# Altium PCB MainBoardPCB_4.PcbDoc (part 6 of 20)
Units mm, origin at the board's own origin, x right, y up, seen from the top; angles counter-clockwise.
Board outline 333.63 x 349.38 mm, 16 copper layers (L1, L2 (GND), L3 (Sign), L4 (GND), L5 (Sign), L6 (PWR/GND), L7(PWR/GND), L8 (Plane_GND), L9 (PWR/GND), L10 (PWR/GND), L11 (PWR/GND), L12 (Sign), L13 (GND), L14 (Sign), L15 (GND), L16), stack 2.502 mm thick; 2205 components, 1648 nets, 8314 pads, 3172 vias.
Unrouted connection lines stored in the file: 5141.
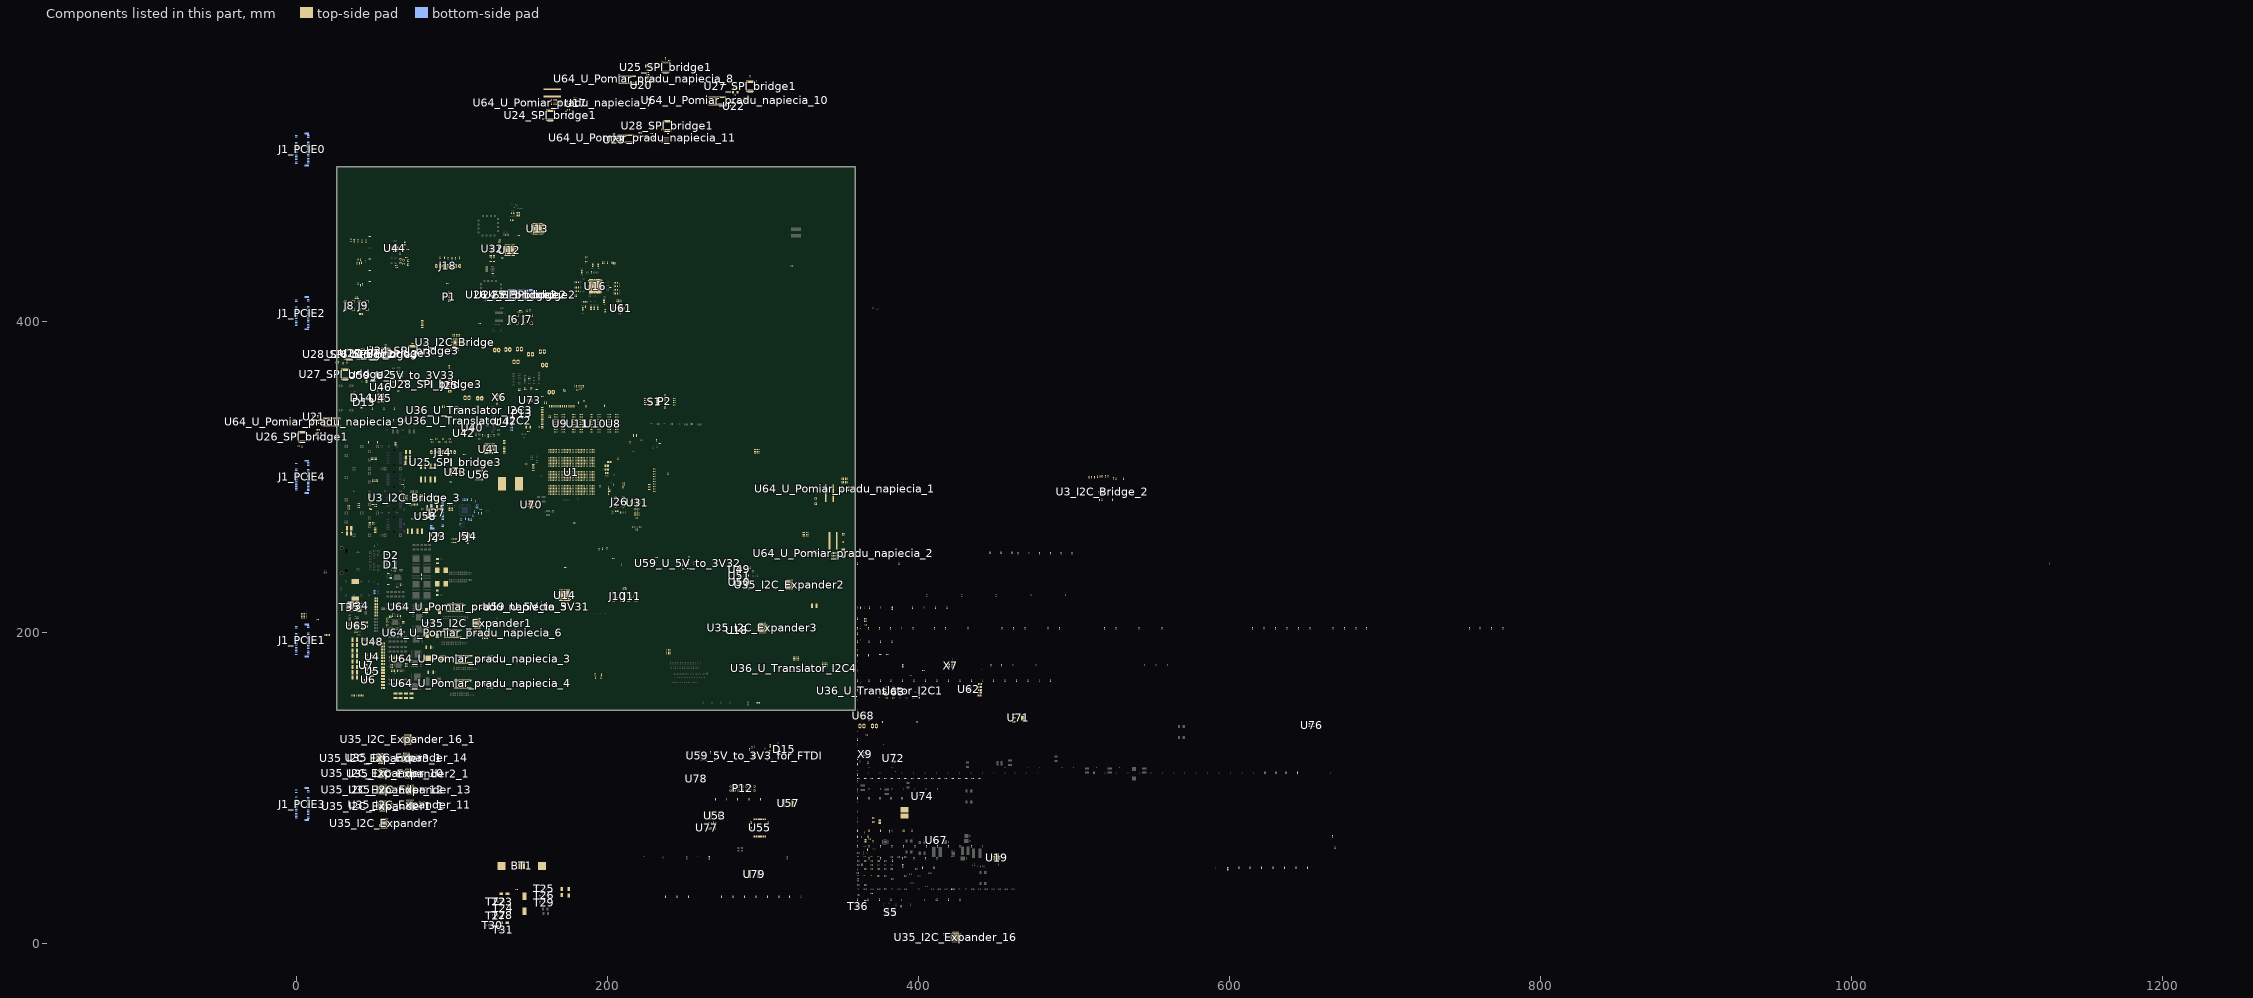
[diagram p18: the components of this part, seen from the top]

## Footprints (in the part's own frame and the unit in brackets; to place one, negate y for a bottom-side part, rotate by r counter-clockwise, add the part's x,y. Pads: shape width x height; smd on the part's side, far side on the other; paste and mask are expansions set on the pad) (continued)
"FBVB900 XX" [mm] "BGA, 900-Leads, Body 31,00x31,00mmx2,88mm, Pitch 1,00mm"
  round 0.5 smd: A1(-14.5,14.5) A2(-13.5,14.5) A3(-12.5,14.5) A4(-11.5,14.5) A5(-10.5,14.5) A6(-9.5,14.5) A7(-8.5,14.5) A8(-7.5,14.5) A9(-6.5,14.5) A10(-5.5,14.5) A11(-4.5,14.5) A12(-3.5,14.5) A13(-2.5,14.5) A14(-1.5,14.5) A15(-0.5,14.5) A16(0.5,14.5) A17(1.5,14.5) A18(2.5,14.5) A19(3.5,14.5) A20(4.5,14.5) A21(5.5,14.5) A22(6.5,14.5) A23(7.5,14.5) A24(8.5,14.5) A25(9.5,14.5) A26(10.5,14.5) A27(11.5,14.5) A28(12.5,14.5) A29(13.5,14.5) A30(14.5,14.5) AA1(-14.5,-5.5) AA2(-13.5,-5.5) AA3(-12.5,-5.5) AA4(-11.5,-5.5) AA5(-10.5,-5.5) AA6(-9.5,-5.5) AA7(-8.5,-5.5) AA8(-7.5,-5.5) AA9(-6.5,-5.5) AA10(-5.5,-5.5) AA11(-4.5,-5.5) AA12(-3.5,-5.5) AA13(-2.5,-5.5) AA14(-1.5,-5.5) AA15(-0.5,-5.5) AA16(0.5,-5.5) AA17(1.5,-5.5) AA18(2.5,-5.5) AA19(3.5,-5.5) AA20(4.5,-5.5) AA21(5.5,-5.5) AA22(6.5,-5.5) AA23(7.5,-5.5) AA24(8.5,-5.5) AA25(9.5,-5.5) AA26(10.5,-5.5) AA27(11.5,-5.5) AA28(12.5,-5.5) AA29(13.5,-5.5) AA30(14.5,-5.5) AB1(-14.5,-6.5) AB2(-13.5,-6.5) AB3(-12.5,-6.5) AB4(-11.5,-6.5) AB5(-10.5,-6.5) AB6(-9.5,-6.5) AB7(-8.5,-6.5) AB8(-7.5,-6.5) AB9(-6.5,-6.5) AB10(-5.5,-6.5) AB11(-4.5,-6.5) AB12(-3.5,-6.5) AB13(-2.5,-6.5) AB14(-1.5,-6.5) AB15(-0.5,-6.5) AB16(0.5,-6.5) AB17(1.5,-6.5) AB18(2.5,-6.5) AB19(3.5,-6.5) AB20(4.5,-6.5) AB21(5.5,-6.5) AB22(6.5,-6.5) AB23(7.5,-6.5) AB24(8.5,-6.5) AB25(9.5,-6.5) AB26(10.5,-6.5) AB27(11.5,-6.5) AB28(12.5,-6.5) AB29(13.5,-6.5) AB30(14.5,-6.5) AC1(-14.5,-7.5) AC2(-13.5,-7.5) AC3(-12.5,-7.5) AC4(-11.5,-7.5) AC5(-10.5,-7.5) AC6(-9.5,-7.5) AC7(-8.5,-7.5) AC8(-7.5,-7.5) AC9(-6.5,-7.5) AC10(-5.5,-7.5) AC11(-4.5,-7.5) AC12(-3.5,-7.5) AC13(-2.5,-7.5) AC14(-1.5,-7.5) AC15(-0.5,-7.5) AC16(0.5,-7.5) AC17(1.5,-7.5) AC18(2.5,-7.5) AC19(3.5,-7.5) AC20(4.5,-7.5) AC21(5.5,-7.5) AC22(6.5,-7.5) AC23(7.5,-7.5) AC24(8.5,-7.5) AC25(9.5,-7.5) AC26(10.5,-7.5) AC27(11.5,-7.5) AC28(12.5,-7.5) AC29(13.5,-7.5) AC30(14.5,-7.5) AD1(-14.5,-8.5) AD2(-13.5,-8.5) AD3(-12.5,-8.5) AD4(-11.5,-8.5) AD5(-10.5,-8.5) AD6(-9.5,-8.5) AD7(-8.5,-8.5) AD8(-7.5,-8.5) AD9(-6.5,-8.5) AD10(-5.5,-8.5) AD11(-4.5,-8.5) AD12(-3.5,-8.5) AD13(-2.5,-8.5) AD14(-1.5,-8.5) AD15(-0.5,-8.5) AD16(0.5,-8.5) AD17(1.5,-8.5) AD18(2.5,-8.5) AD19(3.5,-8.5) AD20(4.5,-8.5) AD21(5.5,-8.5) AD22(6.5,-8.5) AD23(7.5,-8.5) AD24(8.5,-8.5) AD25(9.5,-8.5) AD26(10.5,-8.5) AD27(11.5,-8.5) AD28(12.5,-8.5) AD29(13.5,-8.5) AD30(14.5,-8.5) AE1(-14.5,-9.5) AE2(-13.5,-9.5) AE3(-12.5,-9.5) AE4(-11.5,-9.5) AE5(-10.5,-9.5) AE6(-9.5,-9.5) AE7(-8.5,-9.5) AE8(-7.5,-9.5) AE9(-6.5,-9.5) AE10(-5.5,-9.5) AE11(-4.5,-9.5) AE12(-3.5,-9.5) AE13(-2.5,-9.5) AE14(-1.5,-9.5) AE15(-0.5,-9.5) AE16(0.5,-9.5) AE17(1.5,-9.5) AE18(2.5,-9.5) AE19(3.5,-9.5) AE20(4.5,-9.5) AE21(5.5,-9.5) AE22(6.5,-9.5) AE23(7.5,-9.5) AE24(8.5,-9.5) AE25(9.5,-9.5) AE26(10.5,-9.5) AE27(11.5,-9.5) AE28(12.5,-9.5) AE29(13.5,-9.5) AE30(14.5,-9.5) AF1(-14.5,-10.5) AF2(-13.5,-10.5) AF3(-12.5,-10.5) AF4(-11.5,-10.5) AF5(-10.5,-10.5) AF6(-9.5,-10.5) AF7(-8.5,-10.5) AF8(-7.5,-10.5) AF9(-6.5,-10.5) AF10(-5.5,-10.5) AF11(-4.5,-10.5) AF12(-3.5,-10.5) AF13(-2.5,-10.5) AF14(-1.5,-10.5) AF15(-0.5,-10.5) AF16(0.5,-10.5) AF17(1.5,-10.5) AF18(2.5,-10.5) AF19(3.5,-10.5) AF20(4.5,-10.5) AF21(5.5,-10.5) AF22(6.5,-10.5) AF23(7.5,-10.5) AF24(8.5,-10.5) AF25(9.5,-10.5) AF26(10.5,-10.5) AF27(11.5,-10.5) AF28(12.5,-10.5) AF29(13.5,-10.5) AF30(14.5,-10.5) AG1(-14.5,-11.5) AG2(-13.5,-11.5) AG3(-12.5,-11.5) AG4(-11.5,-11.5) AG5(-10.5,-11.5) AG6(-9.5,-11.5) AG7(-8.5,-11.5) AG8(-7.5,-11.5) AG9(-6.5,-11.5) AG10(-5.5,-11.5) AG11(-4.5,-11.5) AG12(-3.5,-11.5) AG13(-2.5,-11.5) AG14(-1.5,-11.5) AG15(-0.5,-11.5) AG16(0.5,-11.5) AG17(1.5,-11.5) AG18(2.5,-11.5) AG19(3.5,-11.5) AG20(4.5,-11.5) AG21(5.5,-11.5) AG22(6.5,-11.5) AG23(7.5,-11.5) AG24(8.5,-11.5) AG25(9.5,-11.5) AG26(10.5,-11.5) AG27(11.5,-11.5) AG28(12.5,-11.5) AG29(13.5,-11.5) AG30(14.5,-11.5) AH1(-14.5,-12.5) AH2(-13.5,-12.5) AH3(-12.5,-12.5) AH4(-11.5,-12.5) AH5(-10.5,-12.5) AH6(-9.5,-12.5) AH7(-8.5,-12.5) AH8(-7.5,-12.5) AH9(-6.5,-12.5) AH10(-5.5,-12.5) AH11(-4.5,-12.5) AH12(-3.5,-12.5) AH13(-2.5,-12.5) AH14(-1.5,-12.5) AH15(-0.5,-12.5) AH16(0.5,-12.5) AH17(1.5,-12.5) AH18(2.5,-12.5) AH19(3.5,-12.5) AH20(4.5,-12.5) AH21(5.5,-12.5) AH22(6.5,-12.5) AH23(7.5,-12.5) AH24(8.5,-12.5) AH25(9.5,-12.5) AH26(10.5,-12.5) AH27(11.5,-12.5) AH28(12.5,-12.5) AH29(13.5,-12.5) AH30(14.5,-12.5) AJ1(-14.5,-13.5) AJ2(-13.5,-13.5) AJ3(-12.5,-13.5) AJ4(-11.5,-13.5) AJ5(-10.5,-13.5) AJ6(-9.5,-13.5) AJ7(-8.5,-13.5) AJ8(-7.5,-13.5) AJ9(-6.5,-13.5) AJ10(-5.5,-13.5) AJ11(-4.5,-13.5) AJ12(-3.5,-13.5) AJ13(-2.5,-13.5) AJ14(-1.5,-13.5) AJ15(-0.5,-13.5) AJ16(0.5,-13.5) AJ17(1.5,-13.5) AJ18(2.5,-13.5) AJ19(3.5,-13.5) AJ20(4.5,-13.5) AJ21(5.5,-13.5) AJ22(6.5,-13.5) AJ23(7.5,-13.5) AJ24(8.5,-13.5) AJ25(9.5,-13.5) AJ26(10.5,-13.5) AJ27(11.5,-13.5) AJ28(12.5,-13.5) AJ29(13.5,-13.5) AJ30(14.5,-13.5) AK1(-14.5,-14.5) AK2(-13.5,-14.5) AK3(-12.5,-14.5) AK4(-11.5,-14.5) AK5(-10.5,-14.5) AK6(-9.5,-14.5) AK7(-8.5,-14.5) AK8(-7.5,-14.5) AK9(-6.5,-14.5) AK10(-5.5,-14.5) AK11(-4.5,-14.5) AK12(-3.5,-14.5) AK13(-2.5,-14.5) AK14(-1.5,-14.5) AK15(-0.5,-14.5) AK16(0.5,-14.5) AK17(1.5,-14.5) AK18(2.5,-14.5) AK19(3.5,-14.5) AK20(4.5,-14.5) AK21(5.5,-14.5) AK22(6.5,-14.5) AK23(7.5,-14.5) AK24(8.5,-14.5) AK25(9.5,-14.5) AK26(10.5,-14.5) AK27(11.5,-14.5) AK28(12.5,-14.5) AK29(13.5,-14.5) AK30(14.5,-14.5) B1(-14.5,13.5) B2(-13.5,13.5) B3(-12.5,13.5) B4(-11.5,13.5) B5(-10.5,13.5) B6(-9.5,13.5) B7(-8.5,13.5) B8(-7.5,13.5) B9(-6.5,13.5) B10(-5.5,13.5) B11(-4.5,13.5) B12(-3.5,13.5) B13(-2.5,13.5) B14(-1.5,13.5) B15(-0.5,13.5) B16(0.5,13.5) B17(1.5,13.5) B18(2.5,13.5) B19(3.5,13.5) B20(4.5,13.5) B21(5.5,13.5) B22(6.5,13.5) B23(7.5,13.5) B24(8.5,13.5) B25(9.5,13.5) B26(10.5,13.5) B27(11.5,13.5) B28(12.5,13.5) B29(13.5,13.5) B30(14.5,13.5) C1(-14.5,12.5) C2(-13.5,12.5) C3(-12.5,12.5) C4(-11.5,12.5) C5(-10.5,12.5) C6(-9.5,12.5) C7(-8.5,12.5) C8(-7.5,12.5) C9(-6.5,12.5) C10(-5.5,12.5) C11(-4.5,12.5) C12(-3.5,12.5) C13(-2.5,12.5) C14(-1.5,12.5) C15(-0.5,12.5) C16(0.5,12.5) C17(1.5,12.5) C18(2.5,12.5) C19(3.5,12.5) C20(4.5,12.5) C21(5.5,12.5) C22(6.5,12.5) C23(7.5,12.5) C24(8.5,12.5) C25(9.5,12.5) C26(10.5,12.5) C27(11.5,12.5) C28(12.5,12.5) C29(13.5,12.5) C30(14.5,12.5) D1(-14.5,11.5) D2(-13.5,11.5) D3(-12.5,11.5) D4(-11.5,11.5) D5(-10.5,11.5) D6(-9.5,11.5) D7(-8.5,11.5) D8(-7.5,11.5) D9(-6.5,11.5) D10(-5.5,11.5) D11(-4.5,11.5) D12(-3.5,11.5) D13(-2.5,11.5) D14(-1.5,11.5) D15(-0.5,11.5) D16(0.5,11.5) D17(1.5,11.5) D18(2.5,11.5) D19(3.5,11.5) D20(4.5,11.5) D21(5.5,11.5) D22(6.5,11.5) D23(7.5,11.5) D24(8.5,11.5) D25(9.5,11.5) D26(10.5,11.5) D27(11.5,11.5) D28(12.5,11.5) D29(13.5,11.5) D30(14.5,11.5) E1(-14.5,10.5) E2(-13.5,10.5) E3(-12.5,10.5) E4(-11.5,10.5) E5(-10.5,10.5) E6(-9.5,10.5) E7(-8.5,10.5) E8(-7.5,10.5) E9(-6.5,10.5) E10(-5.5,10.5) E11(-4.5,10.5) E12(-3.5,10.5) E13(-2.5,10.5) E14(-1.5,10.5) E15(-0.5,10.5) E16(0.5,10.5) E17(1.5,10.5) E18(2.5,10.5) E19(3.5,10.5) E20(4.5,10.5) E21(5.5,10.5) E22(6.5,10.5) E23(7.5,10.5) E24(8.5,10.5) E25(9.5,10.5) E26(10.5,10.5) E27(11.5,10.5) E28(12.5,10.5) E29(13.5,10.5) E30(14.5,10.5) F1(-14.5,9.5) F2(-13.5,9.5) F3(-12.5,9.5) F4(-11.5,9.5) F5(-10.5,9.5) F6(-9.5,9.5) F7(-8.5,9.5) F8(-7.5,9.5) F9(-6.5,9.5) F10(-5.5,9.5) F11(-4.5,9.5) F12(-3.5,9.5) F13(-2.5,9.5) F14(-1.5,9.5) F15(-0.5,9.5) F16(0.5,9.5) F17(1.5,9.5) F18(2.5,9.5) F19(3.5,9.5) F20(4.5,9.5) F21(5.5,9.5) F22(6.5,9.5) F23(7.5,9.5) F24(8.5,9.5) F25(9.5,9.5) F26(10.5,9.5) F27(11.5,9.5) F28(12.5,9.5) F29(13.5,9.5) F30(14.5,9.5) G1(-14.5,8.5) G2(-13.5,8.5) G3(-12.5,8.5) G4(-11.5,8.5) G5(-10.5,8.5) G6(-9.5,8.5) G7(-8.5,8.5) G8(-7.5,8.5) G9(-6.5,8.5) G10(-5.5,8.5) G11(-4.5,8.5) G12(-3.5,8.5) G13(-2.5,8.5) G14(-1.5,8.5) G15(-0.5,8.5) G16(0.5,8.5) G17(1.5,8.5) G18(2.5,8.5) G19(3.5,8.5) G20(4.5,8.5) G21(5.5,8.5) G22(6.5,8.5) G23(7.5,8.5) G24(8.5,8.5) G25(9.5,8.5) G26(10.5,8.5) G27(11.5,8.5) G28(12.5,8.5) G29(13.5,8.5) G30(14.5,8.5) H1(-14.5,7.5) H2(-13.5,7.5) H3(-12.5,7.5) H4(-11.5,7.5) H5(-10.5,7.5) H6(-9.5,7.5) H7(-8.5,7.5) H8(-7.5,7.5) H9(-6.5,7.5) H10(-5.5,7.5) H11(-4.5,7.5) H12(-3.5,7.5) H13(-2.5,7.5) H14(-1.5,7.5) H15(-0.5,7.5) H16(0.5,7.5) H17(1.5,7.5) H18(2.5,7.5) H19(3.5,7.5) H20(4.5,7.5) H21(5.5,7.5) H22(6.5,7.5) H23(7.5,7.5) H24(8.5,7.5) H25(9.5,7.5) H26(10.5,7.5) H27(11.5,7.5) H28(12.5,7.5) H29(13.5,7.5) H30(14.5,7.5) J1(-14.5,6.5) J2(-13.5,6.5) J3(-12.5,6.5) J4(-11.5,6.5) J5(-10.5,6.5) J6(-9.5,6.5) J7(-8.5,6.5) J8(-7.5,6.5) J9(-6.5,6.5) J10(-5.5,6.5) J11(-4.5,6.5) J12(-3.5,6.5) J13(-2.5,6.5) J14(-1.5,6.5) J15(-0.5,6.5) J16(0.5,6.5) J17(1.5,6.5) J18(2.5,6.5) J19(3.5,6.5) J20(4.5,6.5) J21(5.5,6.5) J22(6.5,6.5) J23(7.5,6.5) J24(8.5,6.5) J25(9.5,6.5) J26(10.5,6.5) J27(11.5,6.5) J28(12.5,6.5) J29(13.5,6.5) J30(14.5,6.5) K1(-14.5,5.5) K2(-13.5,5.5) K3(-12.5,5.5) K4(-11.5,5.5) K5(-10.5,5.5) K6(-9.5,5.5) K7(-8.5,5.5) K8(-7.5,5.5) K9(-6.5,5.5) K10(-5.5,5.5) K11(-4.5,5.5) K12(-3.5,5.5) K13(-2.5,5.5) K14(-1.5,5.5) K15(-0.5,5.5) K16(0.5,5.5) K17(1.5,5.5) K18(2.5,5.5) K19(3.5,5.5) K20(4.5,5.5) K21(5.5,5.5) K22(6.5,5.5) K23(7.5,5.5) K24(8.5,5.5) K25(9.5,5.5) K26(10.5,5.5) K27(11.5,5.5) K28(12.5,5.5) K29(13.5,5.5) K30(14.5,5.5) L1(-14.5,4.5) L2(-13.5,4.5) L3(-12.5,4.5) L4(-11.5,4.5) L5(-10.5,4.5) L6(-9.5,4.5) L7(-8.5,4.5) L8(-7.5,4.5) L9(-6.5,4.5) L10(-5.5,4.5) L11(-4.5,4.5) L12(-3.5,4.5) L13(-2.5,4.5) L14(-1.5,4.5) L15(-0.5,4.5) L16(0.5,4.5) L17(1.5,4.5) L18(2.5,4.5) L19(3.5,4.5) L20(4.5,4.5) L21(5.5,4.5) L22(6.5,4.5) L23(7.5,4.5) L24(8.5,4.5) L25(9.5,4.5) L26(10.5,4.5) L27(11.5,4.5) L28(12.5,4.5) L29(13.5,4.5) L30(14.5,4.5) M1(-14.5,3.5) M2(-13.5,3.5) M3(-12.5,3.5) M4(-11.5,3.5) M5(-10.5,3.5) M6(-9.5,3.5) M7(-8.5,3.5) M8(-7.5,3.5) M9(-6.5,3.5) M10(-5.5,3.5) M11(-4.5,3.5) M12(-3.5,3.5) M13(-2.5,3.5) M14(-1.5,3.5) M15(-0.5,3.5) M16(0.5,3.5) M17(1.5,3.5) M18(2.5,3.5) M19(3.5,3.5) M20(4.5,3.5) M21(5.5,3.5) M22(6.5,3.5) M23(7.5,3.5) M24(8.5,3.5) M25(9.5,3.5) M26(10.5,3.5) M27(11.5,3.5) M28(12.5,3.5) M29(13.5,3.5) M30(14.5,3.5) N1(-14.5,2.5) N2(-13.5,2.5) N3(-12.5,2.5) N4(-11.5,2.5) N5(-10.5,2.5) N6(-9.5,2.5) N7(-8.5,2.5) N8(-7.5,2.5) N9(-6.5,2.5) N10(-5.5,2.5) N11(-4.5,2.5) N12(-3.5,2.5) N13(-2.5,2.5) N14(-1.5,2.5) N15(-0.5,2.5) N16(0.5,2.5) N17(1.5,2.5) N18(2.5,2.5) N19(3.5,2.5) N20(4.5,2.5) N21(5.5,2.5) N22(6.5,2.5) N23(7.5,2.5) N24(8.5,2.5) N25(9.5,2.5) N26(10.5,2.5) N27(11.5,2.5) N28(12.5,2.5) N29(13.5,2.5) N30(14.5,2.5) P1(-14.5,1.5) P2(-13.5,1.5) P3(-12.5,1.5) P4(-11.5,1.5) P5(-10.5,1.5) P6(-9.5,1.5) P7(-8.5,1.5) P8(-7.5,1.5) P9(-6.5,1.5) P10(-5.5,1.5) P11(-4.5,1.5) P12(-3.5,1.5) P13(-2.5,1.5) P14(-1.5,1.5) P15(-0.5,1.5) P16(0.5,1.5) P17(1.5,1.5) P18(2.5,1.5) P19(3.5,1.5) P20(4.5,1.5) P21(5.5,1.5) P22(6.5,1.5) P23(7.5,1.5) P24(8.5,1.5) P25(9.5,1.5) P26(10.5,1.5) P27(11.5,1.5) P28(12.5,1.5) P29(13.5,1.5) P30(14.5,1.5) R1(-14.5,0.5) R2(-13.5,0.5) R3(-12.5,0.5) R4(-11.5,0.5) R5(-10.5,0.5) R6(-9.5,0.5) R7(-8.5,0.5) R8(-7.5,0.5) R9(-6.5,0.5) R10(-5.5,0.5) R11(-4.5,0.5) R12(-3.5,0.5) R13(-2.5,0.5) R14(-1.5,0.5) R15(-0.5,0.5) R16(0.5,0.5) R17(1.5,0.5) R18(2.5,0.5) R19(3.5,0.5) R20(4.5,0.5) R21(5.5,0.5) R22(6.5,0.5) R23(7.5,0.5) R24(8.5,0.5) R25(9.5,0.5) R26(10.5,0.5) R27(11.5,0.5) R28(12.5,0.5) R29(13.5,0.5) R30(14.5,0.5) T1(-14.5,-0.5) T2(-13.5,-0.5) T3(-12.5,-0.5) T4(-11.5,-0.5) T5(-10.5,-0.5) T6(-9.5,-0.5) T7(-8.5,-0.5) T8(-7.5,-0.5) T9(-6.5,-0.5) T10(-5.5,-0.5) T11(-4.5,-0.5) T12(-3.5,-0.5) T13(-2.5,-0.5) T14(-1.5,-0.5) T15(-0.5,-0.5) T16(0.5,-0.5) T17(1.5,-0.5) T18(2.5,-0.5) T19(3.5,-0.5) T20(4.5,-0.5) T21(5.5,-0.5) T22(6.5,-0.5) T23(7.5,-0.5) T24(8.5,-0.5) T25(9.5,-0.5) T26(10.5,-0.5) T27(11.5,-0.5) T28(12.5,-0.5) T29(13.5,-0.5) T30(14.5,-0.5) U1(-14.5,-1.5) U2(-13.5,-1.5) U3(-12.5,-1.5) U4(-11.5,-1.5) U5(-10.5,-1.5) U6(-9.5,-1.5) U7(-8.5,-1.5) U8(-7.5,-1.5) U9(-6.5,-1.5) U10(-5.5,-1.5) U11(-4.5,-1.5) U12(-3.5,-1.5) U13(-2.5,-1.5) U14(-1.5,-1.5) U15(-0.5,-1.5) U16(0.5,-1.5) U17(1.5,-1.5) U18(2.5,-1.5) U19(3.5,-1.5) U20(4.5,-1.5) U21(5.5,-1.5) U22(6.5,-1.5) U23(7.5,-1.5) U24(8.5,-1.5) U25(9.5,-1.5) U26(10.5,-1.5) U27(11.5,-1.5) U28(12.5,-1.5) U29(13.5,-1.5) U30(14.5,-1.5) V1(-14.5,-2.5) V2(-13.5,-2.5) V3(-12.5,-2.5) V4(-11.5,-2.5) V5(-10.5,-2.5) V6(-9.5,-2.5) V7(-8.5,-2.5) V8(-7.5,-2.5) V9(-6.5,-2.5) V10(-5.5,-2.5) V11(-4.5,-2.5) V12(-3.5,-2.5) V13(-2.5,-2.5) V14(-1.5,-2.5) V15(-0.5,-2.5) V16(0.5,-2.5) V17(1.5,-2.5) V18(2.5,-2.5) V19(3.5,-2.5) V20(4.5,-2.5) V21(5.5,-2.5) V22(6.5,-2.5) V23(7.5,-2.5) V24(8.5,-2.5) V25(9.5,-2.5) V26(10.5,-2.5) V27(11.5,-2.5) V28(12.5,-2.5) V29(13.5,-2.5) V30(14.5,-2.5) W1(-14.5,-3.5) W2(-13.5,-3.5) W3(-12.5,-3.5) W4(-11.5,-3.5) W5(-10.5,-3.5) W6(-9.5,-3.5) W7(-8.5,-3.5) W8(-7.5,-3.5) W9(-6.5,-3.5) W10(-5.5,-3.5) W11(-4.5,-3.5) W12(-3.5,-3.5) W13(-2.5,-3.5) W14(-1.5,-3.5) W15(-0.5,-3.5) W16(0.5,-3.5) W17(1.5,-3.5) W18(2.5,-3.5) W19(3.5,-3.5) W20(4.5,-3.5) W21(5.5,-3.5) W22(6.5,-3.5) W23(7.5,-3.5) W24(8.5,-3.5) W25(9.5,-3.5) W26(10.5,-3.5) W27(11.5,-3.5) W28(12.5,-3.5) W29(13.5,-3.5) W30(14.5,-3.5) Y1(-14.5,-4.5) Y2(-13.5,-4.5) Y3(-12.5,-4.5) Y4(-11.5,-4.5) Y5(-10.5,-4.5) Y6(-9.5,-4.5) Y7(-8.5,-4.5) Y8(-7.5,-4.5) Y9(-6.5,-4.5) Y10(-5.5,-4.5) Y11(-4.5,-4.5) Y12(-3.5,-4.5) Y13(-2.5,-4.5) Y14(-1.5,-4.5) Y15(-0.5,-4.5) Y16(0.5,-4.5) Y17(1.5,-4.5) Y18(2.5,-4.5) Y19(3.5,-4.5) Y20(4.5,-4.5) Y21(5.5,-4.5) Y22(6.5,-4.5) Y23(7.5,-4.5) Y24(8.5,-4.5) Y25(9.5,-4.5) Y26(10.5,-4.5) Y27(11.5,-4.5) Y28(12.5,-4.5) Y29(13.5,-4.5) Y30(14.5,-4.5)
  silkscreen extent -16.27,-15.5 15.5,15.5, body extent -15.5,-15.5 15.5,15.5, height 2.88
FC0H224ZFTBR24 [mm] "Super-CAP Aluminum Electrolytic Capacitor, Body 10,80x10,80x11,00mm, IPC High Density"
  rect 4.6x2.5 smd: 1(4.8,0) 2(-4.8,0)
  silkscreen extent -5.5,-5.5 5.5,5.5, body extent -6.1,-5.5 6.1,5.5, height 11
FC-135R/FC-135 [mm] "Crystal Unit,32,768kHz, 2-Leads, Body 3,20x1,50mm, IPC Medium Density"
  rect 1x1.8 smd: 1(-1.25,0) 2(1.25,0)
  silkscreen extent -0.07,-0.8 0.08,0.8, body extent -1.65,-0.8 1.65,0.8, height 0.8
FCSL110R005FERCT-ND [mm] "Wide 4320 (11050 Metric), 2043"
  rect 1.05x11.2 smd: 1(-2.3,0) 2(2.3,0)
  silkscreen extent -1.4,-5.5 1.4,5.5, body extent -2.8,-5.6 2.8,5.6, height 0.8
"FER 0603/1608" [mm] "Chip Ferrite, 2-Leads, Body 1.60x0.80mm, IPC Medium Density"
  rect 0.9x1 smd: 1(-0.675,0) 2(0.675,0)
  silkscreen extent -1.4,-0.7 1.4,0.7, body extent -0.8,-0.41 0.8,0.41, height 0.82
"FER 0805/2012" [mm] "Chip Ferrite, 2-Leads, Body 2.00x1.20mm, IPC Medium Density"
  rect 1.3x1.4 smd: 1(-0.8,0) 2(0.8,0)
  silkscreen extent -1.7,-0.9 1.7,0.9, body extent -1,-0.64 1,0.64, height 1.26
FPF2895C-D [mm] "BGA, 24-Leads, Body 1,67x2,60mmx0,61mm, Pitch 0,40mm"
  round 0.23 smd: A1(-0.6,1) A2(-0.2,1) A3(0.2,1) A4(0.6,1) B1(-0.6,0.6) B2(-0.2,0.6) B3(0.2,0.6) B4(0.6,0.6) C1(-0.6,0.2) C2(-0.2,0.2) C3(0.2,0.2) C4(0.6,0.2) D1(-0.6,-0.2) D2(-0.2,-0.2) D3(0.2,-0.2) D4(0.6,-0.2) E1(-0.6,-0.6) E2(-0.2,-0.6) E3(0.2,-0.6) E4(0.6,-0.6) F1(-0.6,-1) F2(-0.2,-1) F3(0.2,-1) F4(0.6,-1)
  silkscreen extent -0.99,1.36 -0.89,1.45, body extent -0.83,-1.3 0.83,1.3, height 0.61
FT4232HL [mm] "LQFP-64 Package Dimensions"
  rect 1.1x0.22 smd: 1(-5.55,3.75) 2(-5.55,3.25) 3(-5.55,2.75) 4(-5.55,2.25) 5(-5.55,1.75) 6(-5.55,1.25) 7(-5.55,0.75) 8(-5.55,0.25) 9(-5.55,-0.25) 10(-5.55,-0.75) 11(-5.55,-1.25) 12(-5.55,-1.75) 13(-5.55,-2.25) 14(-5.55,-2.75) 15(-5.55,-3.25) 16(-5.55,-3.75) 33(5.55,-3.75) 34(5.55,-3.25) 35(5.55,-2.75) 36(5.55,-2.25) 37(5.55,-1.75) 38(5.55,-1.25) 39(5.55,-0.75) 40(5.55,-0.25) 41(5.55,0.25) 42(5.55,0.75) 43(5.55,1.25) 44(5.55,1.75) 45(5.55,2.25) 46(5.55,2.75) 47(5.55,3.25) 48(5.55,3.75)
  rect 0.22x1.1 smd: 17(-3.75,-5.55) 18(-3.25,-5.55) 19(-2.75,-5.55) 20(-2.25,-5.55) 21(-1.75,-5.55) 22(-1.25,-5.55) 23(-0.75,-5.55) 24(-0.25,-5.55) 25(0.25,-5.55) 26(0.75,-5.55) 27(1.25,-5.55) 28(1.75,-5.55) 29(2.25,-5.55) 30(2.75,-5.55) 31(3.25,-5.55) 32(3.75,-5.55) 49(3.75,5.55) 50(3.25,5.55) 51(2.75,5.55) 52(2.25,5.55) 53(1.75,5.55) 54(1.25,5.55) 55(0.75,5.55) 56(0.25,5.55) 57(-0.25,5.55) 58(-0.75,5.55) 59(-1.25,5.55) 60(-1.75,5.55) 61(-2.25,5.55) 62(-2.75,5.55) 63(-3.25,5.55) 64(-3.75,5.55)
  silkscreen extent -5.67,-4.68 4.68,4.67, body extent -6,-6 6,6, height 1.6
HDR1X2 [mm] "Connector; Header; 2 Position"
  rect 1.5x1.5 hole 0.9: 1(0,0)
  round 1.5 hole 0.9: 2(2.54,0)
  silkscreen extent -1.27,-1.27 3.81,1.27
HDR1X3 [mm] "Connector; Header; 3 Position"
  rect 1.5x1.5 hole 0.9: 1(0,0)
  round 1.5 hole 0.9: 2(2.54,0) 3(5.08,0)
  silkscreen extent -1.27,-1.27 6.35,1.27
HDR1X4 [mm] "Connector; Header; 4 Position"
  rect 1.5x1.5 hole 0.9: 1(0,0)
  round 1.5 hole 0.9: 2(2.54,0) 3(5.08,0) 4(7.62,0)
  silkscreen extent -1.27,-1.27 8.89,1.27
HDR2X7 [mm] "Connector; Header; 7x2 Position"
  rect 1.5x1.5 hole 0.9: 1(0,0)
  round 1.5 hole 0.9: 2(0,2.54) 3(2.54,0) 4(2.54,2.54) 5(5.08,0) 6(5.08,2.54) 7(7.62,0) 8(7.62,2.54) 9(10.16,0) 10(10.16,2.54) 11(12.7,0) 12(12.7,2.54) 13(15.24,0) 14(15.24,2.54)
  silkscreen extent -1.27,-1.27 16.51,3.81
INA226 [mm] "TSSOP, 10-Leads, Body 3,00x3,00mm, Pitch 0,50mm, IPC Medium Density"
  rect 1.45x0.3 smd: 1(-2.2,1) 2(-2.2,0.5) 3(-2.2,0) 4(-2.2,-0.5) 5(-2.2,-1) 6(2.2,-1) 7(2.2,-0.5) 8(2.2,0) 9(2.2,0.5) 10(2.2,1)
  silkscreen extent -2.32,-1.55 1.15,1.82, body extent -2.45,-1.55 2.45,1.55, height 1.1
IP4856CX25/C [mm] "BGA, 25-Leads, Body 2,05x2,05mmx0,55mm, Pitch 0,40mm"
  round 0.2 smd: A1(-0.8,0.8) A2(-0.4,0.8) A3(0,0.8) A4(0.4,0.8) A5(0.8,0.8) B1(-0.8,0.4) B2(-0.4,0.4) B3(0,0.4) B4(0.4,0.4) B5(0.8,0.4) C1(-0.8,0) C2(-0.4,0) C3(0,0) C4(0.4,0) C5(0.8,0) D1(-0.8,-0.4) D2(-0.4,-0.4) D3(0,-0.4) D4(0.4,-0.4) D5(0.8,-0.4) E1(-0.8,-0.8) E2(-0.4,-0.8) E3(0,-0.8) E4(0.4,-0.8) E5(0.8,-0.8)
  silkscreen extent -1.18,1.08 -1.08,1.18, body extent -1.02,-1.03 1.03,1.03, height 0.55
IRLML6401PbF [mm] "SOT23, 3-Leads, Body 2,92x2,37mm, Pitch 0,95mm, IPC High Density"
  rect 0.975x0.802 smd: 1(-0.885,0.95) 2(-0.885,-0.95) 3(0.885,0)
  silkscreen extent -1.01,-1.5 0.7,2.03, body extent -1.32,-1.52 1.32,1.52, height 1.12
ISM330DHCXL [mm] "LGA-14L 2.5x3x0.86 mm"
  rect 0.5x0.25 smd: 1(-1.25,0.75) 2(-1.25,0.25) 3(-1.25,-0.25) 4(-1.25,-0.75) 8(1.25,-0.75) 9(1.25,-0.25) 10(1.25,0.25) 11(1.25,0.75)
  rect 0.25x0.5 smd: 5(-0.5,-1) 6(0,-1) 7(0.5,-1) 12(0.5,1) 13(0,1) 14(-0.5,1)
  silkscreen extent -2.47,-1.45 1.7,1.45, body extent -1.6,-1.35 1.6,1.35, height 0.86
"JST XH B4B-XH-A" [mm]
  oval 1.75x2.5 hole 0.9: 1(-3.75,0) 2(-1.25,0) 3(1.25,0) 4(3.75,0)
  silkscreen extent -6.2,-3.38 6.2,2.38, body extent -6.2,-3.38 6.2,2.38, height 7
"JST XH B7B-XH-A" [mm]
  oval 1.75x2.5 hole 0.9: 1(-7.5,0) 2(-5,0) 3(-2.5,0) 4(0,0) 5(2.5,0) 6(5,0) 7(7.5,0)
  silkscreen extent -9.95,-3.38 9.95,2.38, body extent -9.95,-3.37 9.95,2.38, height 7
"LED 0603/1608 GREEN" [mm] "Chip Diode, 2-Leads, Body 1.60x0.80mm, IPC Medium Density"
  rect 0.8x0.8 smd: 1(-0.75,0) 2(0.75,0)
  silkscreen extent -1.52,-0.7 1.52,0.7, body extent -0.8,-0.4 0.8,0.4, height 0.53
LM3880-Q1 [mm] "SOT23, 6-Leads, Body 2,90x2,80mm, Pitch 0,95mm, IPC High Density"
  rect 1.1x0.6 smd: 1(-1.3,0.95) 2(-1.3,0) 3(-1.3,-0.95) 4(1.3,-0.95) 5(1.3,0) 6(1.3,0.95)
  silkscreen extent -1.42,-1.55 0.5,1.92, body extent -1.5,-1.53 1.5,1.53, height 1.45
LMK05028 [mm] "QFN, 64-Leads, Body 9,15x9,15mm, Pitch 0,50mm, Thermal Pad 7,75x7,75mm, IPC Medium Density"
  oval 0.6x0.24 smd: 1(-4.4,3.75) 2(-4.4,3.25) 3(-4.4,2.75) 4(-4.4,2.25) 5(-4.4,1.75) 6(-4.4,1.25) 7(-4.4,0.75) 8(-4.4,0.25) 9(-4.4,-0.25) 10(-4.4,-0.75) 11(-4.4,-1.25) 12(-4.4,-1.75) 13(-4.4,-2.25) 14(-4.4,-2.75) 15(-4.4,-3.25) 16(-4.4,-3.75) 33(4.4,-3.75) 34(4.4,-3.25) 35(4.4,-2.75) 36(4.4,-2.25) 37(4.4,-1.75) 38(4.4,-1.25) 39(4.4,-0.75) 40(4.4,-0.25) 41(4.4,0.25) 42(4.4,0.75) 43(4.4,1.25) 44(4.4,1.75) 45(4.4,2.25) 46(4.4,2.75) 47(4.4,3.25) 48(4.4,3.75)
  oval 0.24x0.6 smd: 17(-3.75,-4.4) 18(-3.25,-4.4) 19(-2.75,-4.4) 20(-2.25,-4.4) 21(-1.75,-4.4) 22(-1.25,-4.4) 23(-0.75,-4.4) 24(-0.25,-4.4) 25(0.25,-4.4) 26(0.75,-4.4) 27(1.25,-4.4) 28(1.75,-4.4) 29(2.25,-4.4) 30(2.75,-4.4) 31(3.25,-4.4) 32(3.75,-4.4) 49(3.75,4.4) 50(3.25,4.4) 51(2.75,4.4) 52(2.25,4.4) 53(1.75,4.4) 54(1.25,4.4) 55(0.75,4.4) 56(0.25,4.4) 57(-0.25,4.4) 58(-0.75,4.4) 59(-1.25,4.4) 60(-1.75,4.4) 61(-2.25,4.4) 62(-2.75,4.4) 63(-3.25,4.4) 64(-3.75,4.4)
  rect 7.75x7.75 smd paste-300: 65(0,0)
  L1 pour cut-out: 1.975,2.6
  silkscreen extent -5.32,-4.55 4.55,4.55, body extent -4.65,-4.65 4.65,4.65, height 1
LT3042 [mm] "10-Lead Plastic DFN (3mm × 3mm)"
  rect 0.7x0.25 smd: 1(-1.425,1) 2(-1.425,0.5) 3(-1.425,0) 4(-1.425,-0.5) 5(-1.425,-1) 6(1.425,-1) 7(1.425,-0.5) 8(1.425,0) 9(1.425,0.5) 10(1.425,1)
  rect 1.65x2.38 smd paste-0.1: 11(0,0)
  silkscreen extent -2.15,-1.7 1.7,1.75, body extent -1.55,-1.55 1.55,1.55, height 0.75
LT3504 [mm] "UFD Package  28-Lead Plastic QFN (4mm × 5mm)  (Reference LTC DWG # 05-08-1712 Rev B)"
  rect 0.7x0.25 smd: 1(-1.9,1.75) 2(-1.9,1.25) 3(-1.9,0.75) 4(-1.9,0.25) 5(-1.9,-0.25) 6(-1.9,-0.75) 7(-1.9,-1.25) 8(-1.9,-1.75) 15(1.9,-1.75) 16(1.9,-1.25) 17(1.9,-0.75) 18(1.9,-0.25) 19(1.9,0.25) 20(1.9,0.75) 21(1.9,1.25) 22(1.9,1.75)
  rect 0.25x0.7 smd: 9(-1.25,-2.4) 10(-0.75,-2.4) 11(-0.25,-2.4) 12(0.25,-2.4) 13(0.75,-2.4) 14(1.25,-2.4) 23(1.25,2.4) 24(0.75,2.4) 25(0.25,2.4) 26(-0.25,2.4) 27(-0.75,2.4) 28(-1.25,2.4)
  rect 2.65x3.65 smd: 29(0,0)
  silkscreen extent -2.82,-2.55 2.05,2.55, body extent -2.05,-2.55 2.05,2.55, height 0.8
LTC6952 [mm] "PQFN, 52-Leads, Body 7,00x8,00mm, Pitch 0,50mm, Thermal Pad 5,70x6,70mm, IPC High Density"
  rect 0.7x0.25 smd: 1(-3.4,3.25) 2(-3.4,2.75) 3(-3.4,2.25) 4(-3.4,1.75) 5(-3.4,1.25) 6(-3.4,0.75) 7(-3.4,0.25) 8(-3.4,-0.25) 9(-3.4,-0.75) 10(-3.4,-1.25) 11(-3.4,-1.75) 12(-3.4,-2.25) 13(-3.4,-2.75) 14(-3.4,-3.25) 27(3.4,-3.25) 28(3.4,-2.75) 29(3.4,-2.25) 30(3.4,-1.75) 31(3.4,-1.25) 32(3.4,-0.75) 33(3.4,-0.25) 34(3.4,0.25) 35(3.4,0.75) 36(3.4,1.25) 37(3.4,1.75) 38(3.4,2.25) 39(3.4,2.75) 40(3.4,3.25)
  rect 0.25x0.7 smd: 15(-2.75,-3.9) 16(-2.25,-3.9) 17(-1.75,-3.9) 18(-1.25,-3.9) 19(-0.75,-3.9) 20(-0.25,-3.9) 21(0.25,-3.9) 22(0.75,-3.9) 23(1.25,-3.9) 24(1.75,-3.9) 25(2.25,-3.9) 26(2.75,-3.9) 41(2.75,3.9) 42(2.25,3.9) 43(1.75,3.9) 44(1.25,3.9) 45(0.75,3.9) 46(0.25,3.9) 47(-0.25,3.9) 48(-0.75,3.9) 49(-1.25,3.9) 50(-1.75,3.9) 51(-2.25,3.9) 52(-2.75,3.9)
  rect 5.41x6.45 smd: 53(0,0)
  silkscreen extent -4.32,-4.05 3.55,4.05, body extent -3.55,-4.05 3.55,4.05, height 0.8
"M.2 KEY M" [mm]
  rect 0.3x1.55 smd: 1(-9.25,3.825) 2(-9,-3.725) 3(-8.75,3.825) 4(-8.5,-3.725) 5(-8.25,3.825) 6(-8,-3.725) 7(-7.75,3.825) 8(-7.5,-3.725) 9(-7.25,3.825) 10(-7,-3.725) 11(-6.75,3.825) 12(-6.5,-3.725) 13(-6.25,3.825) 14(-6,-3.725) 15(-5.75,3.825) 16(-5.5,-3.725) 17(-5.25,3.825) 18(-5,-3.725) 19(-4.75,3.825) 20(-4.5,-3.725) 21(-4.25,3.825) 22(-4,-3.725) 23(-3.75,3.825) 24(-3.5,-3.725) 25(-3.25,3.825) 26(-3,-3.725) 27(-2.75,3.825) 28(-2.5,-3.725) 29(-2.25,3.825) 30(-2,-3.725) 31(-1.75,3.825) 32(-1.5,-3.725) 33(-1.25,3.825) 34(-1,-3.725) 35(-0.75,3.825) 36(-0.5,-3.725) 37(-0.25,3.825) 38(0,-3.725) 39(0.25,3.825) 40(0.5,-3.725) 41(0.75,3.825) 42(1,-3.725) 43(1.25,3.825) 44(1.5,-3.725) 45(1.75,3.825) 46(2,-3.725) 47(2.25,3.825) 48(2.5,-3.725) 49(2.75,3.825) 50(3,-3.725) 51(3.25,3.825) 52(3.5,-3.725) 53(3.75,3.825) 54(4,-3.725) 55(4.25,3.825) 56(4.5,-3.725) 57(4.75,3.825) 58(5,-3.725) 59(7.25,3.825) 60(7.5,-3.725) 61(7.75,3.825) 62(8,-3.725) 63(8.25,3.825) 64(8.5,-3.725) 65(8.75,3.825) 66(9,-3.725) 67(9.25,3.825)
  rect 1.2x2.75 smd: ""(-10.35,3.05) ""(10.35,3.05)
  silkscreen extent -50.5,-143.6 50,5.45, body extent -50.5,-143.6 50,4.4, height 4.09
"M.2 KEY M - NVMe" [mm]
  rect 0.3x1.55 smd: 1(-9.25,3.825) 2(-9,-3.725) 3(-8.75,3.825) 4(-8.5,-3.725) 5(-8.25,3.825) 6(-8,-3.725) 7(-7.75,3.825) 8(-7.5,-3.725) 9(-7.25,3.825) 10(-7,-3.725) 11(-6.75,3.825) 12(-6.5,-3.725) 13(-6.25,3.825) 14(-6,-3.725) 15(-5.75,3.825) 16(-5.5,-3.725) 17(-5.25,3.825) 18(-5,-3.725) 19(-4.75,3.825) 20(-4.5,-3.725) 21(-4.25,3.825) 22(-4,-3.725) 23(-3.75,3.825) 24(-3.5,-3.725) 25(-3.25,3.825) 26(-3,-3.725) 27(-2.75,3.825) 28(-2.5,-3.725) 29(-2.25,3.825) 30(-2,-3.725) 31(-1.75,3.825) 32(-1.5,-3.725) 33(-1.25,3.825) 34(-1,-3.725) 35(-0.75,3.825) 36(-0.5,-3.725) 37(-0.25,3.825) 38(0,-3.725) 39(0.25,3.825) 40(0.5,-3.725) 41(0.75,3.825) 42(1,-3.725) 43(1.25,3.825) 44(1.5,-3.725) 45(1.75,3.825) 46(2,-3.725) 47(2.25,3.825) 48(2.5,-3.725) 49(2.75,3.825) 50(3,-3.725) 51(3.25,3.825) 52(3.5,-3.725) 53(3.75,3.825) 54(4,-3.725) 55(4.25,3.825) 56(4.5,-3.725) 57(4.75,3.825) 58(5,-3.725) 59(7.25,3.825) 60(7.5,-3.725) 61(7.75,3.825) 62(8,-3.725) 63(8.25,3.825) 64(8.5,-3.725) 65(8.75,3.825) 66(9,-3.725) 67(9.25,3.825)
  rect 1.2x2.75 smd: ""(-10.35,3.05) ""(10.35,3.05)
  silkscreen extent -11.75,-5.7 11.75,5.45, body extent -10.95,-4.3 10.95,4.4, height 4.09
"MAX3051EKA+T SOT23" [mm] "SOT-23, 8L BODY"
  rect 1.3x0.42 smd: 1(-1.175,0.975) 2(-1.175,0.325) 3(-1.175,-0.325) 4(-1.175,-0.975) 5(1.175,-0.975) 6(1.175,-0.325) 7(1.175,0.325) 8(1.175,0.975)
  silkscreen extent -1.3,-1.5 0.5,1.86, body extent -1.39,-1.5 1.39,1.5, height 1.45
MAX16025TE+T [mm] "Thin Quad Flatpack, No Leads; T1644-4;  4.10mm(L) x 4.10mm(W) x 0.80mm(H)"
  rect 0.95x0.35 smd: 1(-1.84,0.975) 2(-1.84,0.325) 3(-1.84,-0.325) 4(-1.84,-0.975) 9(1.84,-0.975) 10(1.84,-0.325) 11(1.84,0.325) 12(1.84,0.975)
  rect 0.35x0.95 smd: 5(-0.975,-1.84) 6(-0.325,-1.84) 7(0.325,-1.84) 8(0.975,-1.84) 13(0.975,1.84) 14(0.325,1.84) 15(-0.325,1.84) 16(-0.975,1.84)
  rect 2.23x2.23 smd: 17(0,0)
  silkscreen extent -2.97,-2.2 2.2,2.2, body extent -2.05,-2.05 2.05,2.05, height 0.8
MAX17557 [mm] "20 TQFN, Maximintegrated 21-0139, Land Pattern Number 90-0037"
  rect 0.95x0.3 smd: 1(-1.84,1) 2(-1.84,0.5) 3(-1.84,0) 4(-1.84,-0.5) 5(-1.84,-1) 11(1.84,-1) 12(1.84,-0.5) 13(1.84,0) 14(1.84,0.5) 15(1.84,1)
  rect 0.3x0.95 smd: 6(-1,-1.84) 7(-0.5,-1.84) 8(0,-1.84) 9(0.5,-1.84) 10(1,-1.84) 16(1,1.84) 17(0.5,1.84) 18(0,1.84) 19(-0.5,1.84) 20(-1,1.84)
  rect 2.23x2.23 smd: 21(0,0)
  silkscreen extent -2.82,-2.05 2.05,2.05, body extent -2.05,-2.05 2.05,2.05, height 1
MCP1727T-ADJE/MF [mm] "SON, 8-Leads, Body 3.00x3.00mm, Pitch 0.65mm, Thermal Pad 2.40x1.60mm, IPC High Density"
  rect 0.6x0.35 smd: 1(-1.3,0.975) 2(-1.3,0.325) 3(-1.3,-0.325) 4(-1.3,-0.975) 5(1.3,-0.975) 6(1.3,-0.325) 7(1.3,0.325) 8(1.3,0.975)
  rect 1.6x2.4 smd: 9(0,0)
  silkscreen extent -2.1,-1.65 1.65,1.7, body extent -1.5,-1.5 1.5,1.5, height 1
MGV0605 [mm] "Precision Wire Wound Inductor, 2-Leads, Body 7,30x6,70mm, IPC High Density"
  rect 2.95x3.5 smd: 1(-2.725,0) 2(2.725,0)
  silkscreen extent -3.9,-3.55 3.9,3.55, body extent -3.75,-3.35 3.75,3.35, height 5.5
"MGV1004 Series" [mm] "Precision Wire Wound Inductor, 2-Leads, Body 11,00x10,00mm, IPC High Density"
  rect 4.1x3.5 smd: 1(-4.75,0) 2(4.75,0)
  silkscreen extent -5.75,-5.15 5.75,5.15, body extent -5.6,-5 5.6,5, height 4.1
"MOLEX KK 0022272021" [mm]
  oval 2x3 hole 1.2: 1(-1.27,0) 2(1.27,0)
  silkscreen extent -2.54,-2.79 2.54,2.79, body extent -2.54,-2.9 2.54,2.9, height 11.7
MT40A512M16JY [mm] "BGA, 96-Leads, Body 8,05x14,05mmx1,10mm, Pitch 0,80mm"
  round 0.42 smd: A1(-3.2,6) A2(-2.4,6) A3(-1.6,6) A4(1.6,6) A5(2.4,6) A6(3.2,6) B1(-3.2,5.2) B2(-2.4,5.2) B3(-1.6,5.2) B4(1.6,5.2) B5(2.4,5.2) B6(3.2,5.2) C1(-3.2,4.4) C2(-2.4,4.4) C3(-1.6,4.4) C4(1.6,4.4) C5(2.4,4.4) C6(3.2,4.4) D1(-3.2,3.6) D2(-2.4,3.6) D3(-1.6,3.6) D4(1.6,3.6) D5(2.4,3.6) D6(3.2,3.6) E1(-3.2,2.8) E2(-2.4,2.8) E3(-1.6,2.8) E4(1.6,2.8) E5(2.4,2.8) E6(3.2,2.8) F1(-3.2,2) F2(-2.4,2) F3(-1.6,2) F4(1.6,2) F5(2.4,2) F6(3.2,2) G1(-3.2,1.2) G2(-2.4,1.2) G3(-1.6,1.2) G4(1.6,1.2) G5(2.4,1.2) G6(3.2,1.2) H1(-3.2,0.4) H2(-2.4,0.4) H3(-1.6,0.4) H4(1.6,0.4) H5(2.4,0.4) H6(3.2,0.4) J1(-3.2,-0.4) J2(-2.4,-0.4) J3(-1.6,-0.4) J4(1.6,-0.4) J5(2.4,-0.4) J6(3.2,-0.4) K1(-3.2,-1.2) K2(-2.4,-1.2) K3(-1.6,-1.2) K4(1.6,-1.2) K5(2.4,-1.2) K6(3.2,-1.2) L1(-3.2,-2) L2(-2.4,-2) L3(-1.6,-2) L4(1.6,-2) L5(2.4,-2) L6(3.2,-2) M1(-3.2,-2.8) M2(-2.4,-2.8) M3(-1.6,-2.8) M4(1.6,-2.8) M5(2.4,-2.8) M6(3.2,-2.8) N1(-3.2,-3.6) N2(-2.4,-3.6) N3(-1.6,-3.6) N4(1.6,-3.6) N5(2.4,-3.6) N6(3.2,-3.6) P1(-3.2,-4.4) P2(-2.4,-4.4) P3(-1.6,-4.4) P4(1.6,-4.4) P5(2.4,-4.4) P6(3.2,-4.4) R1(-3.2,-5.2) R2(-2.4,-5.2) R3(-1.6,-5.2) R4(1.6,-5.2) R5(2.4,-5.2) R6(3.2,-5.2) T1(-3.2,-6) T2(-2.4,-6) T3(-1.6,-6) T4(1.6,-6) T5(2.4,-6) T6(3.2,-6)
  silkscreen extent -4.8,-7.03 4.02,7.02, body extent -4.09,-7.15 3.96,6.9, height 1.1
"MTFC8GAKAJCN-4M IT TR" [mm] "BGA, 156-Leads, Body 11,50x13,00mmx1,00mm, Pitch 0,50mm"
  round 0.3 smd: A1(-3.25,3.25) A2(-2.75,3.25) A3(-2.25,3.25) A4(-1.75,3.25) A5(-1.25,3.25) A6(-0.75,3.25) A7(-0.25,3.25) A8(0.25,3.25) A9(0.75,3.25) A10(1.25,3.25) A11(1.75,3.25) A12(2.25,3.25) A13(2.75,3.25) A14(3.25,3.25) B1(-3.25,2.75) B2(-2.75,2.75) B3(-2.25,2.75) B4(-1.75,2.75) B5(-1.25,2.75) B6(-0.75,2.75) B7(-0.25,2.75) B8(0.25,2.75) B9(0.75,2.75) B10(1.25,2.75) B11(1.75,2.75) B12(2.25,2.75) B13(2.75,2.75) B14(3.25,2.75) C1(-3.25,2.25) C2(-2.75,2.25) C3(-2.25,2.25) C4(-1.75,2.25) C5(-1.25,2.25) C6(-0.75,2.25) C7(-0.25,2.25) C8(0.25,2.25) C9(0.75,2.25) C10(1.25,2.25) C11(1.75,2.25) C12(2.25,2.25) C13(2.75,2.25) C14(3.25,2.25) D1(-3.25,1.75) D2(-2.75,1.75) D3(-2.25,1.75) D4(-1.75,1.75) D12(2.25,1.75) D13(2.75,1.75) D14(3.25,1.75) E1(-3.25,1.25) E2(-2.75,1.25) E3(-2.25,1.25) E5(-1.25,1.25) E6(-0.75,1.25) E7(-0.25,1.25) E8(0.25,1.25) E9(0.75,1.25) E10(1.25,1.25) E12(2.25,1.25) E13(2.75,1.25) E14(3.25,1.25) F1(-3.25,0.75) F2(-2.75,0.75) F3(-2.25,0.75) F5(-1.25,0.75) F10(1.25,0.75) F12(2.25,0.75) F13(2.75,0.75) F14(3.25,0.75) G1(-3.25,0.25) G2(-2.75,0.25) G3(-2.25,0.25) G5(-1.25,0.25) G10(1.25,0.25) G12(2.25,0.25) G13(2.75,0.25) G14(3.25,0.25) H1(-3.25,-0.25) H2(-2.75,-0.25) H3(-2.25,-0.25) H5(-1.25,-0.25) H10(1.25,-0.25) H12(2.25,-0.25) H13(2.75,-0.25) H14(3.25,-0.25) J1(-3.25,-0.75) J2(-2.75,-0.75) J3(-2.25,-0.75) J5(-1.25,-0.75) J10(1.25,-0.75) J12(2.25,-0.75) J13(2.75,-0.75) J14(3.25,-0.75) K1(-3.25,-1.25) K2(-2.75,-1.25) K3(-2.25,-1.25) K5(-1.25,-1.25) K6(-0.75,-1.25) K7(-0.25,-1.25) K8(0.25,-1.25) K9(0.75,-1.25) K10(1.25,-1.25) K12(2.25,-1.25) K13(2.75,-1.25) K14(3.25,-1.25) L1(-3.25,-1.75) L2(-2.75,-1.75) L3(-2.25,-1.75) L12(2.25,-1.75) L13(2.75,-1.75) L14(3.25,-1.75) M1(-3.25,-2.25) M2(-2.75,-2.25) M3(-2.25,-2.25) M4(-1.75,-2.25) M5(-1.25,-2.25) M6(-0.75,-2.25) M7(-0.25,-2.25) M8(0.25,-2.25) M9(0.75,-2.25) M10(1.25,-2.25) M11(1.75,-2.25) M12(2.25,-2.25) M13(2.75,-2.25) M14(3.25,-2.25) N1(-3.25,-2.75) N2(-2.75,-2.75) N3(-2.25,-2.75) N4(-1.75,-2.75) N5(-1.25,-2.75) N6(-0.75,-2.75) N7(-0.25,-2.75) N8(0.25,-2.75) N9(0.75,-2.75) N10(1.25,-2.75) N11(1.75,-2.75) N12(2.25,-2.75) N13(2.75,-2.75) N14(3.25,-2.75) P1(-3.25,-3.25) P2(-2.75,-3.25) P3(-2.25,-3.25) P4(-1.75,-3.25) P5(-1.25,-3.25) P6(-0.75,-3.25) P7(-0.25,-3.25) P8(0.25,-3.25) P9(0.75,-3.25) P10(1.25,-3.25) P11(1.75,-3.25) P12(2.25,-3.25) P13(2.75,-3.25) P14(3.25,-3.25)
  silkscreen extent -6.52,-6.5 5.75,6.5, body extent -5.75,-6.5 5.75,6.5, height 1
NC7WZ07FHX [mm] "6-UFDFN, 6-MicroPak2™"
  rect 0.57x0.2 smd: 1(-0.365,0.35)
  rect 0.52x0.2 smd: 2(-0.365,0) 3(-0.365,-0.35) 4(0.365,-0.35) 5(0.365,0) 6(0.365,0.35)
  silkscreen extent -0.91,0.61 -0.81,0.71, body extent -0.53,-0.53 0.53,0.53, height 0.55
NRS8040 [mm] "Precision Wire Wound Inductor, 2-Leads, Body 4,00x4,00mm, IPC High Density"
  rect 1.2x3.7 smd: 1(-1.4,0) 2(1.4,0)
  body extent -2.1,-2 2.1,2, height 1.9
PCA9306 [mm] "8-XFDFN, Body 1,40x1,00mm, Pitch 0,35mm, IPC High Density"
  rect 0.53x0.2 smd: 1(-0.335,0.525) 2(-0.335,0.175) 3(-0.335,-0.175) 4(-0.335,-0.525) 5(0.335,-0.525) 6(0.335,-0.175) 7(0.335,0.175) 8(0.335,0.525)
  silkscreen extent -0.86,0.79 -0.76,0.89, body extent -0.53,-0.72 0.53,0.72, height 0.4
PIN1 [mm] "Connector; Plug"
  rect 1.5x1.5 hole 0.9: 1(0,0)
  silkscreen extent -1.4,-1.4 1.4,2.17
PU5931 [mm] "Chip Resistor, 2-Leads, Body 15,00x7,75mm, IPC High Density"
  rect 5.2x8.75 smd: 1(-5.4,0) 2(5.4,0)
  silkscreen extent -2.75,-4.28 2.75,4.28, body extent -7.63,-4 7.63,4, height 1.18
QFN-ML28_N [mm] "QFN, 28-Leads, Body 6x6mm, Pitch 0.65mm, Thermal Pad 4.2x4.2mm, IPC Medium Density"
  oval 1.05x0.3 smd: 1(-2.875,1.95) 2(-2.875,1.3) 3(-2.875,0.65) 4(-2.875,0) 5(-2.875,-0.65) 6(-2.875,-1.3) 7(-2.875,-1.95) 15(2.875,-1.95) 16(2.875,-1.3) 17(2.875,-0.65) 18(2.875,0) 19(2.875,0.65) 20(2.875,1.3) 21(2.875,1.95)
  oval 0.3x1.05 smd: 8(-1.95,-2.875) 9(-1.3,-2.875) 10(-0.65,-2.875) 11(0,-2.875) 12(0.65,-2.875) 13(1.3,-2.875) 14(1.95,-2.875) 22(1.95,2.875) 23(1.3,2.875) 24(0.65,2.875) 25(0,2.875) 26(-0.65,2.875) 27(-1.3,2.875) 28(-1.95,2.875)
  rect 4.2x4.2 smd: 29(0,0)
  silkscreen extent -3.97,-3.2 3.2,3.2, body extent -3.05,-3.05 3.05,3.05, height 1
"RES 0201/0603" [mm] "Chip Resistor, 2-Leads, Body 0.60x0.30mm, IPC Medium Density"
  rect 0.44x0.35 smd: 1(-0.325,0) 2(0.325,0)
  silkscreen extent -0.7,-0.33 0.7,0.33, body extent -0.3,-0.15 0.3,0.15, height 0.21
"RES 0402/1005" [mm] "Chip Resistor, 2-Leads, Body 1.0x0.5mm, IPC Medium Density"
  rect 0.75x0.6 smd: 1(-0.575,0) 2(0.575,0)
  silkscreen extent -1.14,-0.51 1.14,0.51, body extent -0.5,-0.25 0.5,0.25, height 0.35
"RES 0402/1005 RF" [mm] "Chip Resistor, 2-Leads, Body 1.0x0.5mm, IPC High Density"
  rect 0.7x0.6 smd: 1(-0.45,0) 2(0.45,0)
  silkscreen extent -1.02,-0.51 1.02,0.51, body extent -0.5,-0.25 0.5,0.25, height 0.35
"RES 0805/2012 RF" [mm] "Chip Resistor, 2-Leads, Body 2.00x1.25mm, IPC High Density"
  rect 0.95x1.25 smd: 1(-0.775,0) 2(0.775,0)
  silkscreen extent -1.5,-0.8 1.5,0.8, body extent -0.95,-0.62 1.05,0.63, height 0.6
"RES 1206/3216" [mm] "Chip Resistor, 2-Leads, Body 3.13x1.55mm, IPC Medium Density"
  rect 1.2x1.65 smd: 1(-1.4,0) 2(1.4,0)
  silkscreen extent -2.3,-1.1 2.3,1.1, body extent -1.57,-0.8 1.62,0.8, height 0.6
RES_1210 [mm]
  rect 0.9x2.3 smd: 1(-1.55,0) 2(1.55,0)
  silkscreen extent -0.4,-1.05 0.4,1.05, body extent -1.67,-1.33 1.68,1.33, height 0.65
RJK0651DPB [mm] "LFPAK, PTZZ0005DA-A"
  rect 1.1x0.5 smd: 1(-2.65,1.905) 2(-2.65,0.635) 3(-2.65,-0.635) 4(-2.65,-1.905)
  rect 4.5x3.3 smd: 5(0.85,0)
  silkscreen extent -2.77,2.58 -2.53,2.83, body extent -3.05,-2.65 2.95,2.65, height 1.1
S1M-13-F [mm] "Molded Diode, 2-Leads, Body 4,30x2,61mm, IPC High Density"
  rect 2.5x1.7 smd: 1(-2,0) 2(2,0)
  silkscreen extent -3.13,-1.5 2.3,1.52, body extent -2.52,-1.46 2.52,1.46, height 2.4
Si510 [mm] "4-Leads, Body 5,00x3,20mm, Pitch 2,54mm, IPC High Density"
  rect 1.7x1.35 smd: 1(-1.3,1.27) 2(-1.3,-1.27) 3(1.3,-1.27) 4(1.3,1.27)
  silkscreen extent -2.2,-2.65 1.75,2.7, body extent -1.6,-2.5 1.6,2.5, height 1.28
SI2342DS-T1-GE3 [mm] "SOT23, 3-Leads, Body 2,92x2,37mm, Pitch 0,95mm, IPC High Density"
  rect 0.724x0.6 smd: 1(-0.984,0.95) 2(-0.984,-0.95) 3(0.984,0)
  silkscreen extent -1.11,-1.5 0.7,1.92, body extent -1.32,-1.52 1.32,1.52, height 1.12
SI53323-B-GM [mm] "QFN, 16-Leads, Body 3,00x3,00mm, Pitch 0,50mm, Thermal Pad 1,75x1,75mm, IPC High Density"
  rect 0.8x0.3 smd: 1(-1.5,0.75) 2(-1.5,0.25) 3(-1.5,-0.25) 4(-1.5,-0.75) 9(1.5,-0.75) 10(1.5,-0.25) 11(1.5,0.25) 12(1.5,0.75)
  rect 0.3x0.8 smd: 5(-0.75,-1.5) 6(-0.25,-1.5) 7(0.25,-1.5) 8(0.75,-1.5) 13(0.75,1.5) 14(0.25,1.5) 15(-0.25,1.5) 16(-0.75,1.5)
  rect 1.75x1.75 smd: 17(0,0)
  silkscreen extent -2.42,-1.65 1.65,1.65, body extent -1.5,-1.5 1.5,1.5, height 0.9
SiJ482DP [mm] "PowerPAK® SO-8L Case Outline 1"
  rect 0.82x0.41 smd: 1(-2.715,1.905) 2(-2.715,0.635) 3(-2.715,-0.635) 4(-2.715,-1.905)
  rect 3.63x4.061 smd: 5(0.75,0)
  rect 0.61x0.595 smd: ""(-0.05,2.286) ""(-0.05,-2.286)
  rect 0.51x5 smd: ""(2.8,0)
  silkscreen extent -2.84,-2.65 -1.47,2.78, body extent -2.67,-2.63 3.48,2.63, height 1.14
SiT1602B [mm] "2.5 x 2.0 x 0.75 mm"
  rect 1.1x1 smd: 1(-0.95,-0.75) 2(0.95,-0.75) 3(0.95,0.75) 4(-0.95,0.75)
  silkscreen extent -1.76,-1.31 -1.66,-1.21, body extent -1.28,-1.02 1.28,1.02, height 0.8
SLVU2.8-4 [mm] "SOIC-8 Pins 8"
  rect 1.3x0.6 smd: 1(-2.75,1.905) 2(-2.75,0.635) 3(-2.75,-0.635) 4(-2.75,-1.905) 5(2.75,-1.905) 6(2.75,-0.635) 7(2.75,0.635) 8(2.75,1.905)
  silkscreen extent -2.87,-2.5 1.6,2.88, body extent -3,-2.5 3,2.5, height 1.75
SN74AXC4T774PWR [mm] "TSOP,PW0016A, 16-Leads, Body 5,00x4,40mm, Pitch 0,65mm, IPC High Density"
  rect 1.5x0.45 smd: 1(-2.9,2.275) 2(-2.9,1.625) 3(-2.9,0.975) 4(-2.9,0.325) 5(-2.9,-0.325) 6(-2.9,-0.975) 7(-2.9,-1.625) 8(-2.9,-2.275) 9(2.9,-2.275) 10(2.9,-1.625) 11(2.9,-0.975) 12(2.9,-0.325) 13(2.9,0.325) 14(2.9,0.975) 15(2.9,1.625) 16(2.9,2.275)
  silkscreen extent -3.02,-2.55 1.85,3.17, body extent -3.2,-2.55 3.2,2.55, height 1.2
SN74LVC1G08DBVR [mm] "SOT23, 5-Leads, Body 2,90x2,80mm, Pitch 0,95mm, IPC High Density"
  rect 1.1x0.6 smd: 1(-1.3,0.95) 2(-1.3,0) 3(-1.3,-0.95) 4(1.3,-0.95) 5(1.3,0.95)
  silkscreen extent -1.42,-1.55 0.5,1.92, body extent -1.5,-1.53 1.5,1.53, height 1.45
SO8_N [mm] "SOIC, 8-Leads, Body 4.9x3.9mm, Pitch 1.27mm, IPC Medium Density"
  oval 2.2x0.6 smd: 1(-2.4,1.905) 2(-2.4,0.635) 3(-2.4,-0.635) 4(-2.4,-1.905) 5(2.4,-1.905) 6(2.4,-0.635) 7(2.4,0.635) 8(2.4,1.905)
  silkscreen extent -2.53,-2.5 0.9,2.88, body extent -2,-2.5 2,2.5, height 1.75
SRP1265A-220M [mm] "Precision Wire Wound Inductor, 2-Leads, Body 13,50x12,50mm, IPC High Density"
  rect 3.1x5 smd: 1(-5.55,0) 2(5.55,0)
  silkscreen extent -7,-6.4 7,6.4, body extent -6.85,-6.25 6.85,6.25, height 6.6
ST1L08 [mm] "DFN8 (2x3 mm) package outline"
  rect 0.5x0.3 smd: 1(-1.4,0.75) 2(-1.4,0.25) 3(-1.4,-0.25) 4(-1.4,-0.75) 5(1.4,-0.75) 6(1.4,-0.25) 7(1.4,0.25) 8(1.4,0.75)
  rect 1.9x1.75 smd: 9(0,0)
  silkscreen extent -1.91,1.06 -1.81,1.16, body extent -1.5,-1 1.5,1, height 0.9
TCA9548 [mm]
  rect 0.6x0.26 smd: 1(-1.935,1.25) 2(-1.935,0.75) 3(-1.935,0.25) 4(-1.935,-0.25) 5(-1.935,-0.75) 6(-1.935,-1.25) 13(1.935,-1.25) 14(1.935,-0.75) 15(1.935,-0.25) 16(1.935,0.25) 17(1.935,0.75) 18(1.935,1.25)
  rect 0.26x0.6 smd: 7(-1.25,-1.935) 8(-0.75,-1.935) 9(-0.25,-1.935) 10(0.25,-1.935) 11(0.75,-1.935) 12(1.25,-1.935) 19(1.25,1.935) 20(0.75,1.935) 21(0.25,1.935) 22(-0.25,1.935) 23(-0.75,1.935) 24(-1.25,1.935)
  rect 2.1x2.1 smd paste-100: 25(0,0)
  silkscreen extent -2.88,-2 2,2
TECO-5-1814832-1_V [mm] "THD, 5-Leads, Body 6.4x6.4mm, Pitch 5.08mm"
  round 2 hole 1.5: 1(0,0)
  round 2.1 hole 1.6: 2(-2.54,2.54) 3(-2.54,-2.54) 4(2.54,-2.54) 5(2.54,2.54)
  silkscreen extent -3.2,-3.2 3.2,3.2, body extent -3.21,-3.21 3.19,3.19, height 9.5
TECO-640456-2_V [mm] "HDR, 2-Leads, Body 5.715x5.08mm, Pitch 2.54mm"
  rect 1.8x1.8 hole 1.3: 1(1.27,0)
  round 1.8 hole 1.3: 2(-1.27,0)
  silkscreen extent -2.54,-2.54 3.26,3.17, body extent -2.54,-2.67 2.54,3.17, height 10.49
TECO-1909763-1_V [mm] "SMD, 3-Leads, Body 2.6x2.6mm, Height 1.25mm"
  rect 1.05x2.2 smd: 1(-1.475,0) 3(1.475,0)
  rect 1x1.05 smd: 2(0,-1.525)
  silkscreen extent -1.9,-1.77 0.55,1.3, body extent -1.5,-1.55 1.5,1.55, height 1.25
TestPoint [mm] "TestPoint,  Body 1,00x2,54x4,60mm, IPC Low Density"
  silkscreen extent -0.37,-1.27 0.5,1.27, body extent -1.27,-1.27 1.26,1.27, height 4.6
TPD2EUSB30 [mm] "SOT23, 3-Leads, Body 1,00x1,00mm, Pitch 0,35mm, IPC High Density"
  rect 0.3x0.3 smd: 1(-0.425,0.35) 2(-0.425,-0.35) 3(0.425,0)
  silkscreen extent -0.55,-0.55 0.43,1.17, body extent -0.6,-0.53 0.6,0.53, height 0.5
TPD4EUSB30 [mm] "DQA0010A, 10-Leads, Body 2,50x1,00mm, Pitch 0,50mm, IPC High Density"
  rect 0.565x0.2 smd: 1(-0.417,1) 2(-0.418,0.5) 4(-0.417,-0.5) 5(-0.417,-1) 6(0.417,-1) 7(0.417,-0.5) 9(0.417,0.5) 10(0.417,1)
  rect 0.565x0.4 smd paste-0.04: 3(-0.417,0) 8(0.417,0)
  silkscreen extent -1,-1.45 0.55,1.5, body extent -0.63,-1.3 0.63,1.3, height 0.55
TPS7A88 [mm] "RTJ (S-PWQFN-N20) 20-Leads, Body 4,00x4,00mm, Pitch 0,50mm, Thermal Pad 2,70x2,70mm, IPC High Density"
  rect 0.85x0.28 smd: 1(-1.975,1) 2(-1.975,0.5) 3(-1.975,0) 4(-1.975,-0.5) 5(-1.975,-1) 11(1.975,-1) 12(1.975,-0.5) 13(1.975,0) 14(1.975,0.5) 15(1.975,1)
  rect 0.28x0.85 smd: 6(-1,-1.975) 7(-0.5,-1.975) 8(0,-1.975) 9(0.5,-1.975) 10(1,-1.975) 16(1,1.975) 17(0.5,1.975) 18(0,1.975) 19(-0.5,1.975) 20(-1,1.975)
  rect 2.7x2.7 smd paste-3: 21(0,0)
  silkscreen extent -2.85,-2.08 2.07,2.07, body extent -2.07,-2.07 2.07,2.07, height 0.8
TPS212x [mm] "VQFN-HR - 1 mm max height"
  rect 1.05x0.4 smd: 1(-0.675,0.35) 2(-0.675,-0.35) 7(0.675,-0.35) 8(0.675,0.35)
  rect 0.2x0.6 smd: 3(-0.75,-1.15) 4(-0.25,-1.15) 5(0.25,-1.15) 6(0.75,-1.15) 9(0.75,1.15) 10(0.25,1.15) 11(-0.25,1.15) 12(-0.75,1.15)
  silkscreen extent -1.82,-1.3 1.05,1.3, body extent -1.05,-1.3 1.05,1.3, height 1
"TSX-3225 24.0000MF15X-AC6" [mm] "Ceramic Package, 4-Leads, Body 2,50x3,20mm, Pitch 1,60mm, IPC High Density"
  rect 1.4x1.15 smd: 1(-1.1,-0.8) 2(1.1,-0.8) 3(1.1,0.8) 4(-1.1,0.8)
  silkscreen extent -2,-1.7 -1.9,-1.6, body extent -1.6,-1.25 1.6,1.25, height 0.6
UA78M [mm] "SOT223, 4-Leads, DCY (R-PDSO-G4)"
  rect 2.15x0.95 smd: 1(-2.9,2.3) 2(-2.9,0) 3(-2.9,-2.3)
  rect 2.15x3.25 smd: 2(2.9,0)
  silkscreen extent -3.02,-3.35 2.05,3.45, body extent -3.5,-3.35 3.5,3.35, height 1.8
USB3320 [mm] "32-PIN QFN, 5X5MM BODY, 0.5MM PITCH"
  rect 0.75x0.25 smd: 1(-2.45,1.75) 2(-2.45,1.25) 3(-2.45,0.75) 4(-2.45,0.25) 5(-2.45,-0.25) 6(-2.45,-0.75) 7(-2.45,-1.25) 8(-2.45,-1.75) 17(2.45,-1.75) 18(2.45,-1.25) 19(2.45,-0.75) 20(2.45,-0.25) 21(2.45,0.25) 22(2.45,0.75) 23(2.45,1.25) 24(2.45,1.75)
  rect 0.25x0.75 smd: 9(-1.75,-2.45) 10(-1.25,-2.45) 11(-0.75,-2.45) 12(-0.25,-2.45) 13(0.25,-2.45) 14(0.75,-2.45) 15(1.25,-2.45) 16(1.75,-2.45) 25(1.75,2.45) 26(1.25,2.45) 27(0.75,2.45) 28(0.25,2.45) 29(-0.25,2.45) 30(-0.75,2.45) 31(-1.25,2.45) 32(-1.75,2.45)
  rect 3.3x3.3 smd paste-2: 33(0,0)
  silkscreen extent -3.47,2.43 -3.22,2.67, body extent -2.57,-2.57 2.57,2.57, height 1
WE-CHSA_1011 [mm] "SMT High Current Inductor, 2-Leads, body 10.6x10.6mm"
  rect 2.05x3.6 smd: 1(-4.05,0) 2(4.05,0)
  silkscreen extent -5.45,-5.45 5.45,5.45, body extent -5.3,-5.3 5.3,5.3, height 11
WE-HCC_8070 [mm] "SMT High Current Cube Inductor, 2-Leads, body 7.9x7.9mm"
  rect 2.3x3 smd: 1(-3.35,0) 2(3.35,0)
  silkscreen extent -4.1,-4.1 4.1,4.1, body extent -4.2,-3.95 4.2,3.95, height 7.23
WSHP2818 [mm] "Chip Resistor, 2-Leads, Body 7,10x4,60mm, IPC High Density"
  rect 3.5x5.1 smd: 1(-2.055,0) 2(2.055,0)
  body extent -3.67,-2.42 3.67,2.42, height 1.75

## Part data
B1: "BATT LITH 1.5V 5.5MAH COIN 9.5MM", Capacity=5.5mAh, Manufacturer=Seiko, Supplier Part Number 1=728-1082-ND, Voltage Rating=1.5V
BT1: "WA-BCMC Battery Holder, SMT, Battery Type 2016/2020/2025/2032"
C1_PCIE0 C1_PCIE1 C1_PCIE2 C1_PCIE3 C1_PCIE4 C219 C220 C221 C222 C243 C244 C245 C246 C359 C377 C566_U_5V_to_3V31 C566_U_5V_to_3V32 C566_U_5V_to_3V33: library part Capacitor, Case Code (Imperial)=0402, Case Code (Metric)=1005, Dielectric=X5R, Insulation Resistance=10GR, Manufacturer=Yageo, Manufacturer Part Number=CC0402KRX5R6BB104, Max Operating Temperature=85°C, Min Operating Temperature=-55°C, Package Quantity=1, Supplier Part Number 1=311-1336-1-ND, Tolerance=10%, Voltage Rating=10V
C2_PCIE0 C2_PCIE1 C2_PCIE2 C2_PCIE3 C2_PCIE4 C567_U_5V_to_3V31 C567_U_5V_to_3V32 C567_U_5V_to_3V33: library part Capacitor, "CAP CER 2.2UF 6.3V X5R 0402", Case Code (Imperial)=0402, Case Code (Metric)=1005, Dielectric=X5R, Manufacturer="Taiyo Yuden", Manufacturer Part Number=JMK105BJ225KV-F, Max Operating Temperature=85°C, Min Operating Temperature=-55°C, Package Quantity=10000, Supplier Part Number 1=587-5867-1-ND, Tolerance=10%, Voltage Rating=6.3V
C3_PCIE0 C3_PCIE1 C3_PCIE2 C3_PCIE3 C3_PCIE4: library part Capacitor, Case Code (Imperial)=0603, Case Code (Metric)=1608, Dielectric=X5R, Manufacturer=Samsung, Manufacturer Part Number=CL10A475KP8NNNC, Max Operating Temperature=85°C, Min Operating Temperature=-55°C, Package Quantity=1, Tolerance=10%, Voltage Rating=10V
C4 C5 C6 C7 C12 C13 C14 C15 C38 C40 C212 C214 C216 C218 C766 C767 C768 C769: library part Capacitor, Case Code (Imperial)=1210, Case Code (Metric)=3225, Dielectric=X5R, Manufacturer=Samsung, Manufacturer Part Number=CL32A226KAJNNNE, Max Operating Temperature=85°C, Min Operating Temperature=-55°C, Package Quantity=1, Supplier Part Number 1=1276-1101-1-ND, Tolerance=10%, Voltage=25V
C8 C9 C10 C11 C16 C17 C18 C19 C37 C39 C211 C213 C215 C217 C770 C771 C772 C773: library part Capacitor, Case Code (Imperial)=0402, Case Code (Metric)=1005, Dielectric=X7R, Manufacturer=Murata, Manufacturer Part Number=GRM155R71E104KE14J, Max Operating Temperature=125°C, Min Operating Temperature=-55°C, Package Quantity=50000, Supplier Part Number 1=490-14603-1-ND, Tolerance=10%, Voltage Rating=25V
C20 C21 C22 C23 C28 C29 C30 C31 C574 C575 C581 C774 C775 C776 C777: library part Capacitor, "CAP CER 10UF 25V X5R 0805", Case Code (Imperial)=0805, Case Code (Metric)=2012, Dielectric=X5R, Dielectric Material=Ceramic, Manufacturer=KEMET, Manufacturer Part Number=C0805C106K3PACTU, Max Operating Temperature=85°C, Min Operating Temperature=-55°C, Supplier Part Number 1=399-11939-6-ND, Tolerance=10%, Voltage=25V
C24 C25 C26 C27 C32 C33 C34 C35 C580 C582 C584 C778 C779 C780: library part Capacitor, "CAP CER 4.7UF 25V X5R 0805", Case Code (Imperial)=0805, Case Code (Metric)=2012, Dielectric=X5R, Manufacturer=Murata, Manufacturer Part Number=GRM219R61E475KA73D, Max Operating Temperature=85°C, Min Operating Temperature=-55°C, Package Quantity=4000, Supplier Part Number 1=490-12753-1-ND, Tolerance=10%, Voltage Rating=25V
C36: library part Capacitor, Case/Package=0402, Case Code (Metric)=1005, Dielectric=X7R, Dielectric Material=Ceramic, Manufacturer=KEMET, Manufacturer Part Number=C0402C103K4RACTU, Max Operating Temperature=125°C, Min Operating Temperature=-55°C, Package Quantity=1, Supplier Part Number 1=399-1038-1-ND, Tolerance=10%, Voltage=16V
C41 C42 C43 C44 C47 C48 C49 C50 C51 C52 C340: library part Capacitor, Case Code (Imperial)=0402, Dielectric=X5R, Dielectric Material=Ceramic, Manufacturer=KEMET, Manufacturer Part Number=C0402C105K9PACTU, Max Operating Temperature=85°C, Min Operating Temperature=-55°C, Package Quantity=1, Supplier Part Number 1=399-4873-6-ND, Tolerance=10%, Voltage=6.3V
C45: library part Capacitor, "Cap Ceramic 0.0056uF 25V X7R 10% SMD 0402 125C Paper T/R", Case Code (Imperial)=0402, Case Code (Metric)=1005, Dielectric=X7R, Manufacturer=Yageo, Manufacturer Part Number=CC0402KRX7R8BB562, Max Operating Temperature=125°C, Min Operating Temperature=-55°C, Supplier Part Number 1=311-1718-1-ND, Tolerance=10%, Voltage Rating=25V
